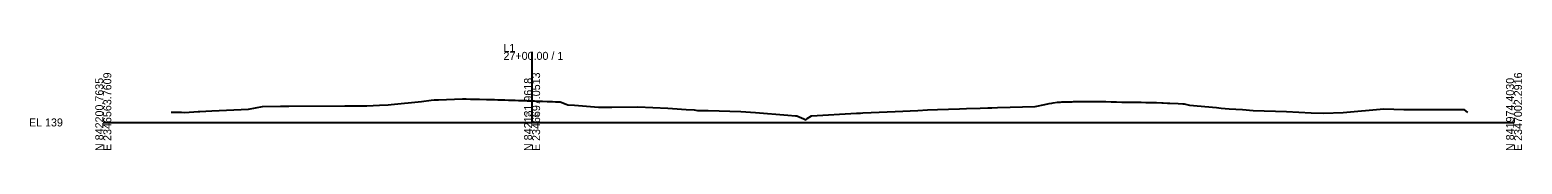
# Model space of a CAD drawing. Extents: x -26 to 2348258, y -10 to 844496.
# Drawn here: x -26 to 496, y -10 to 27 of the extents above; entities that cross this region are included whole.
import ezdxf

# ---------------------------------------------------------------- set-up
doc = ezdxf.new("R2010")
doc.units = 0
for name, color, linetype in [('Exist Cross Section Cell', 7, 'Continuous'), ('Exist XS Center Line Elevation Label', 7, 'Continuous'), ('Exist XS Ground Line', 7, 'Continuous')]:
    doc.layers.add(name, color=color, linetype=linetype)

msp = doc.modelspace()

# ---------------------------------------------------------------- linework, layer by layer
at = {"layer": 'Exist Cross Section Cell'}
for p, q in [((150, 0), (150, 24.69)), ((0, 0), (150, 0)), ((150, 0), (493.51, 0))]:
    msp.add_line(p, q, dxfattribs=at)
at = {"layer": 'Exist XS Ground Line'}
msp.add_lwpolyline([(23.69, 3.65), (27.33, 3.62), (28.58, 3.46), (33.24, 3.83), (33.72, 3.82), (37.98, 4.05), (50.75, 4.62), (55.71, 5.57), (62.02, 5.68), (64.96, 5.72), (84.51, 5.76), (89.56, 5.81), (91.19, 5.77), (92.16, 5.84), (96.62, 6.05), (99.64, 6.21), (100.67, 6.33), (111.36, 7.36), (114.74, 7.74), (115.7, 7.86), (116.11, 7.88), (116.52, 7.89), (117.24, 7.93), (120.1, 8.05), (122.85, 8.15), (125.64, 8.23), (126.27, 8.22), (126.98, 8.21), (128.43, 8.17), (129.3, 8.15), (131.27, 8.11), (131.6, 8.1), (134.08, 8.04), (134.86, 8.02), (136.42, 7.99), (136.91, 7.98), (138.03, 7.94), (139.67, 7.9), (140.41, 7.88), (141.8, 7.84), (142.48, 7.82), (144.08, 7.77), (145.27, 7.72), (145.97, 7.69), (147.29, 7.65), (148.1, 7.62), (148.44, 7.6), (150, 7.55), (150.36, 7.54), (150.8, 7.52), (152.76, 7.45), (153.4, 7.43), (153.7, 7.42), (155.26, 7.36), (156.55, 7.31), (157.12, 7.28), (158.21, 7.2), (159.85, 7.16), (161.96, 6.37), (162.55, 6.17), (164.78, 5.99), (173.21, 5.37), (177.95, 5.36), (186.99, 5.46), (197.51, 4.97), (199.09, 4.88), (203.85, 4.56), (206.67, 4.37), (207.83, 4.15), (211.56, 4.19), (223.04, 3.84), (228.19, 3.48), (239.44, 2.53), (242.1, 2.29), (242.61, 2.26), (245.12, 1.22), (245.77, 0.95), (246.28, 1.37), (247.7, 2.35), (263.53, 3.22), (264.86, 3.3), (265.76, 3.33), (268.61, 3.45), (277.02, 3.81), (284.9, 4.19), (288.27, 4.38), (291.87, 4.5), (299.53, 4.79), (301.97, 4.86), (306.7, 5.01), (309.39, 5.1), (310.78, 5.15), (312.84, 5.18), (326.01, 5.55), (329.33, 6.32), (330.93, 6.65), (331.79, 6.79), (332.32, 6.88), (333.75, 7.1), (334.14, 7.11), (334.8, 7.15), (335.36, 7.17), (336.67, 7.21), (338.04, 7.24), (338.97, 7.26), (339.44, 7.27), (340.87, 7.3), (342.31, 7.31), (342.99, 7.32), (344.25, 7.34), (345.04, 7.34), (346.38, 7.33), (347.89, 7.32), (348.26, 7.31), (349, 7.3), (350.14, 7.28), (350.73, 7.27), (352.52, 7.23), (353.53, 7.21), (354.46, 7.19), (356.3, 7.15), (356.67, 7.14), (357.17, 7.13), (359.13, 7.1), (359.87, 7.09), (361.94, 7.06), (363.11, 7.04), (364.73, 7), (365.33, 6.99), (366.82, 6.96), (367.69, 6.93), (368.39, 6.92), (370.34, 6.84), (370.79, 6.82), (372.31, 6.76), (373.15, 6.73), (376.03, 6.59), (377.62, 6.5), (378.15, 6.48), (379.5, 6.18), (380, 6.08), (389.4, 5.18), (391.04, 5.03), (393.91, 4.81), (398.46, 4.49), (402.2, 4.23), (413.93, 3.77), (422.5, 3.39), (426.83, 3.27), (433.68, 3.49), (447.99, 4.72), (455.01, 4.57), (475.96, 4.52), (477.18, 3.49)], dxfattribs=at)

# ---------------------------------------------------------------- texts
at = {"layer": 'Exist Cross Section Cell'}
for s, p in [('L1', (140, 24.69)), ('27+00.00 / 1', (140, 21.89)), ('EL 139', (-26, -1.4))]:
    msp.add_text(s, height=2.8, dxfattribs=at).set_placement(p)
for s, p in [('E 2346563.7609', (2.8, -10)), ('E 2346697.0513', (152.8, -10)), ('E 2347002.2916', (496.31, -10)), ('N 842200.7635', (0, -10)), ('N 842131.9618', (150, -10)), ('N 841974.4030', (493.51, -10))]:
    msp.add_text(s, height=2.8, rotation=90, dxfattribs=at).set_placement(p)
at = {"layer": 'Exist XS Center Line Elevation Label'}
msp.add_text('146.55', height=1.2, dxfattribs=at).set_placement((147.52, 1.95))

doc.saveas('drawing.dxf')
